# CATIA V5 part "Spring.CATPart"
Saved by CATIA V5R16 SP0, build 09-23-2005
Part number: SPRING
Bounding box of the stored display mesh (mm): x -7.45 to 7.45, y -1.181 to 81.181, z -7.45 to 7.45
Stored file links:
  D:\Format\Downloads\1_SXEDIA_EKSARTHMATON_POU_DINONTAI_ETOIMA (3) (2)\AMORTISER_parts\Spring.CATPart
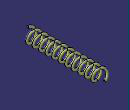
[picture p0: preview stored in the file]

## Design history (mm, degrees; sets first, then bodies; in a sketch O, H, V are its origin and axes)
Body1 (main body)
  Helix1: Direction Y axis, RefPoint {point type OnPlane, Support yz-plane, H 0, V 6.25, Direction (0, 1, 0)}, Pitch 7, Height 80, TaperAngle 0, Revolutions 1
  Sweep1: type Circle, Guide Helix1, Radius 1.2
